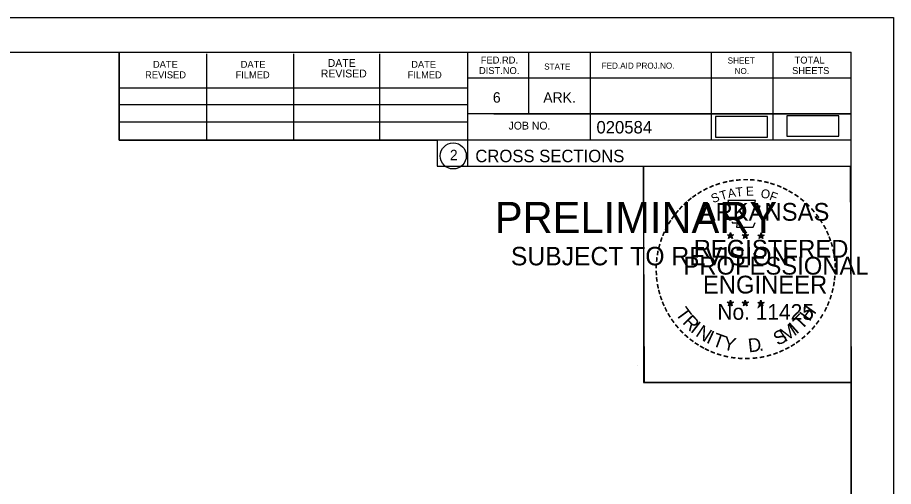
# Model space of a CAD drawing. Extents: x 1312042 to 1371461, y 379929 to 1834241.
# Drawn here: x 1371362.8 to 1371461.2, y 380302.9 to 380355.6 of the extents above; entities that cross this region are included whole.
import ezdxf

# ---------------------------------------------------------------- set-up
doc = ezdxf.new("R2010")
doc.units = 0
for name, color, linetype in [('Default', 7, 'Continuous'), ('R_Border', 7, 'Continuous'), ('R_Border PE', 7, 'Continuous'), ('R_Border Prem', 7, 'Continuous'), ('R_No Plot', 7, 'Continuous')]:
    doc.layers.add(name, color=color, linetype=linetype)

msp = doc.modelspace()

# ---------------------------------------------------------------- linework, layer by layer
at = {"layer": 'Default'}
for points in [[(1371441.216, 380342.147), (1371447.049, 380342.147), (1371447.049, 380344.458), (1371441.216, 380344.458)], [(1371449.239, 380342.253), (1371455.073, 380342.253), (1371455.073, 380344.564), (1371449.239, 380344.564)]]:
    msp.add_lwpolyline(points, close=True, dxfattribs=at)
at = {"layer": 'R_Border'}
for p, q in [((1371140.277, 380351.707), (1371456.457, 380351.707)), ((1371374.197, 380341.827), (1371374.197, 380351.707)), ((1371384.057, 380341.827), (1371384.057, 380351.507)), ((1371393.817, 380341.827), (1371393.817, 380351.507)), ((1371403.497, 380341.827), (1371403.497, 380351.507)), ((1371413.357, 380351.707), (1371413.357, 380338.907)), ((1371420.197, 380351.707), (1371420.197, 380344.767)), ((1371427.137, 380351.707), (1371427.137, 380341.827)), ((1371440.717, 380351.707), (1371440.717, 380341.827)), ((1371447.657, 380351.707), (1371447.657, 380341.827)), ((1371456.457, 380146.247), (1371456.457, 380351.707)), ((1371456.457, 380348.767), (1371413.357, 380348.767)), ((1371456.457, 380348.787), (1371456.457, 380348.787)), ((1371374.197, 380347.687), (1371413.357, 380347.687)), ((1371374.197, 380345.827), (1371413.357, 380345.827)), ((1371456.457, 380344.767), (1371413.357, 380344.767)), ((1371416.317, 380344.767), (1371456.457, 380344.767)), ((1371374.197, 380341.827), (1371374.197, 380343.887)), ((1371374.197, 380343.887), (1371413.357, 380343.887)), ((1371456.457, 380341.827), (1371374.197, 380341.827)), ((1371413.357, 380338.907), (1371456.457, 380338.907))]:
    msp.add_line(p, q, dxfattribs=at)
msp.add_circle((1371411.743, 380340.043), 1.467, dxfattribs=at)
at = {"layer": 'R_Border PE'}
for p, q in [((1371442.541, 380331.162), (1371442.89, 380331.051)), ((1371442.541, 380331.162), (1371442.794, 380331.117)), ((1371442.541, 380331.162), (1371442.778, 380331.04)), ((1371442.674, 380330.754), (1371442.89, 380331.051)), ((1371442.674, 380330.754), (1371442.8, 380330.998)), ((1371442.674, 380330.754), (1371442.888, 380330.971)), ((1371442.89, 380331.416), (1371442.849, 380331.164)), ((1371443.103, 380330.754), (1371442.888, 380330.968)), ((1371442.89, 380331.051), (1371442.89, 380331.416)), ((1371442.89, 380331.416), (1371442.939, 380331.166)), ((1371443.237, 380331.162), (1371442.89, 380331.051)), ((1371443.103, 380330.754), (1371442.89, 380331.051)), ((1371443.237, 380331.162), (1371442.951, 380331.113)), ((1371443.103, 380330.754), (1371442.966, 380331.045)), ((1371443.237, 380331.162), (1371443.033, 380331.06)), ((1371444.211, 380331.162), (1371444.56, 380331.051)), ((1371444.211, 380331.162), (1371444.464, 380331.117)), ((1371444.211, 380331.162), (1371444.448, 380331.04)), ((1371444.344, 380330.754), (1371444.56, 380331.051)), ((1371444.344, 380330.754), (1371444.47, 380330.998)), ((1371444.344, 380330.754), (1371444.558, 380330.971)), ((1371444.56, 380331.416), (1371444.519, 380331.164)), ((1371444.773, 380330.754), (1371444.558, 380330.968)), ((1371444.56, 380331.051), (1371444.56, 380331.416)), ((1371444.56, 380331.416), (1371444.609, 380331.166)), ((1371444.907, 380331.162), (1371444.56, 380331.051)), ((1371444.773, 380330.754), (1371444.56, 380331.051)), ((1371444.907, 380331.162), (1371444.621, 380331.113)), ((1371444.773, 380330.754), (1371444.636, 380331.045)), ((1371444.907, 380331.162), (1371444.703, 380331.06)), ((1371445.975, 380331.15), (1371446.324, 380331.039)), ((1371445.975, 380331.15), (1371446.228, 380331.105)), ((1371445.975, 380331.15), (1371446.212, 380331.028)), ((1371446.108, 380330.742), (1371446.324, 380331.039)), ((1371446.108, 380330.742), (1371446.234, 380330.986)), ((1371446.108, 380330.742), (1371446.322, 380330.959)), ((1371446.324, 380331.404), (1371446.283, 380331.152)), ((1371446.537, 380330.742), (1371446.322, 380330.956)), ((1371446.324, 380331.039), (1371446.324, 380331.404)), ((1371446.324, 380331.404), (1371446.373, 380331.154)), ((1371446.671, 380331.15), (1371446.324, 380331.039)), ((1371446.537, 380330.742), (1371446.324, 380331.039)), ((1371446.671, 380331.15), (1371446.385, 380331.101)), ((1371446.537, 380330.742), (1371446.4, 380331.033)), ((1371446.671, 380331.15), (1371446.467, 380331.048)), ((1371442.537, 380323.589), (1371442.886, 380323.478)), ((1371442.537, 380323.589), (1371442.79, 380323.544)), ((1371442.537, 380323.589), (1371442.774, 380323.467)), ((1371442.886, 380323.843), (1371442.845, 380323.591)), ((1371442.886, 380323.478), (1371442.886, 380323.843)), ((1371442.886, 380323.843), (1371442.935, 380323.593)), ((1371443.233, 380323.589), (1371442.886, 380323.478)), ((1371443.233, 380323.589), (1371442.947, 380323.54)), ((1371443.233, 380323.589), (1371443.029, 380323.487)), ((1371444.206, 380323.589), (1371444.555, 380323.478)), ((1371444.206, 380323.589), (1371444.459, 380323.544)), ((1371444.206, 380323.589), (1371444.443, 380323.467)), ((1371444.555, 380323.843), (1371444.514, 380323.591)), ((1371444.555, 380323.478), (1371444.555, 380323.843)), ((1371444.555, 380323.843), (1371444.604, 380323.593)), ((1371444.902, 380323.589), (1371444.555, 380323.478)), ((1371444.902, 380323.589), (1371444.616, 380323.54)), ((1371444.902, 380323.589), (1371444.698, 380323.487)), ((1371445.973, 380323.579), (1371446.322, 380323.468)), ((1371445.973, 380323.579), (1371446.226, 380323.534)), ((1371445.973, 380323.579), (1371446.21, 380323.457)), ((1371446.322, 380323.833), (1371446.281, 380323.581)), ((1371446.322, 380323.468), (1371446.322, 380323.833)), ((1371446.322, 380323.833), (1371446.371, 380323.583)), ((1371446.669, 380323.579), (1371446.322, 380323.468)), ((1371446.669, 380323.579), (1371446.383, 380323.53)), ((1371446.669, 380323.579), (1371446.465, 380323.477)), ((1371442.67, 380323.181), (1371442.886, 380323.478)), ((1371442.67, 380323.181), (1371442.796, 380323.425)), ((1371442.67, 380323.181), (1371442.884, 380323.398)), ((1371443.099, 380323.181), (1371442.884, 380323.395)), ((1371443.099, 380323.181), (1371442.886, 380323.478)), ((1371443.099, 380323.181), (1371442.962, 380323.472)), ((1371444.339, 380323.181), (1371444.555, 380323.478)), ((1371444.339, 380323.181), (1371444.465, 380323.425)), ((1371444.339, 380323.181), (1371444.553, 380323.398)), ((1371444.768, 380323.181), (1371444.553, 380323.395)), ((1371444.768, 380323.181), (1371444.555, 380323.478)), ((1371444.768, 380323.181), (1371444.631, 380323.472)), ((1371446.106, 380323.171), (1371446.322, 380323.468)), ((1371446.106, 380323.171), (1371446.232, 380323.415)), ((1371446.106, 380323.171), (1371446.32, 380323.388)), ((1371446.535, 380323.171), (1371446.32, 380323.385)), ((1371446.535, 380323.171), (1371446.322, 380323.468)), ((1371446.535, 380323.171), (1371446.398, 380323.462))]:
    msp.add_line(p, q, dxfattribs=at)
for points in [[(1371442.582, 380335.04), (1371442.851, 380334.213)], [(1371446.093, 380334.118), (1371446.235, 380334.402), (1371445.55, 380334.378), (1371445.698, 380335.04), (1371442.582, 380335.04)], [(1371443.074, 380332.617), (1371443.074, 380332.53), (1371443.637, 380332.511), (1371443.583, 380332.038), (1371445.453, 380332.038), (1371445.654, 380332.574)], [(1371442.89, 380331.416), (1371443.103, 380330.754), (1371442.541, 380331.162), (1371443.237, 380331.162), (1371442.674, 380330.754), (1371442.89, 380331.416)], [(1371444.56, 380331.416), (1371444.773, 380330.754), (1371444.211, 380331.162), (1371444.907, 380331.162), (1371444.344, 380330.754), (1371444.56, 380331.416)], [(1371446.324, 380331.404), (1371446.537, 380330.742), (1371445.975, 380331.15), (1371446.671, 380331.15), (1371446.108, 380330.742), (1371446.324, 380331.404)], [(1371442.886, 380323.843), (1371443.099, 380323.181), (1371442.537, 380323.589), (1371443.233, 380323.589), (1371442.67, 380323.181), (1371442.886, 380323.843)], [(1371444.555, 380323.843), (1371444.768, 380323.181), (1371444.206, 380323.589), (1371444.902, 380323.589), (1371444.339, 380323.181), (1371444.555, 380323.843)], [(1371446.322, 380323.833), (1371446.535, 380323.171), (1371445.973, 380323.579), (1371446.669, 380323.579), (1371446.106, 380323.171), (1371446.322, 380323.833)]]:
    msp.add_lwpolyline(points, dxfattribs=at)
for centre, radius in [((1371442.889, 380331.05), 0.172), ((1371442.889, 380331.05), 0.145), ((1371442.889, 380331.05), 0.116), ((1371442.889, 380331.05), 0.0991), ((1371442.889, 380331.05), 0.0747), ((1371442.889, 380331.05), 0.0495), ((1371442.889, 380331.05), 0.0296), ((1371444.559, 380331.05), 0.172), ((1371444.559, 380331.05), 0.145), ((1371444.559, 380331.05), 0.116), ((1371444.559, 380331.05), 0.0991), ((1371444.559, 380331.05), 0.0747), ((1371444.559, 380331.05), 0.0495), ((1371444.559, 380331.05), 0.0296), ((1371446.323, 380331.038), 0.172), ((1371446.323, 380331.038), 0.145), ((1371446.323, 380331.038), 0.116), ((1371446.323, 380331.038), 0.0991), ((1371446.323, 380331.038), 0.0747), ((1371446.323, 380331.038), 0.0495), ((1371446.323, 380331.038), 0.0296), ((1371442.885, 380323.477), 0.172), ((1371442.885, 380323.477), 0.145), ((1371442.885, 380323.477), 0.116), ((1371442.885, 380323.477), 0.0991), ((1371442.885, 380323.477), 0.0747), ((1371444.554, 380323.477), 0.172), ((1371444.554, 380323.477), 0.145), ((1371444.554, 380323.477), 0.116), ((1371444.554, 380323.477), 0.0991), ((1371444.554, 380323.477), 0.0747), ((1371446.321, 380323.467), 0.172), ((1371446.321, 380323.467), 0.145), ((1371446.321, 380323.467), 0.116), ((1371446.321, 380323.467), 0.0991), ((1371442.885, 380323.477), 0.0495), ((1371442.885, 380323.477), 0.0296), ((1371444.554, 380323.477), 0.0495), ((1371444.554, 380323.477), 0.0296), ((1371446.321, 380323.467), 0.0747), ((1371446.321, 380323.467), 0.0495), ((1371446.321, 380323.467), 0.0296)]:
    msp.add_circle(centre, radius, dxfattribs=at)
at = {"layer": 'R_No Plot'}
for p, q in [((1371127.876, 380355.601), (1371461.209, 380355.601)), ((1371432.491, 380316.451), (1371432.491, 380316.451))]:
    msp.add_line(p, q, dxfattribs=at)
for points in [[(1371127.869, 380355.601), (1371461.209, 380355.601), (1371461.209, 380142.264), (1371127.869, 380142.264)], [(1371374.197, 380351.707), (1371374.197, 380341.827), (1371409.929, 380341.827), (1371409.929, 380338.907), (1371433.128, 380338.907), (1371433.128, 380314.574), (1371456.457, 380314.574), (1371456.457, 380146.247), (1371140.277, 380146.247), (1371140.277, 380351.707)], [(1371433.128, 380338.907), (1371456.336, 380338.907), (1371456.457, 380314.574), (1371433.249, 380314.574)]]:
    msp.add_lwpolyline(points, close=True, dxfattribs=at)

# ---------------------------------------------------------------- texts
at = {"layer": 'R_Border'}
for s, height, p in [('FED.RD.', 0.7819, (1371414.837, 380350.427)), ('SHEET', 0.684, (1371442.577, 380350.427)), ('TOTAL', 0.7819, (1371450.097, 380350.427)), ('DATE', 0.7819, (1371377.997, 380349.947)), ('DATE', 0.7819, (1371387.857, 380349.947)), ('DATE', 0.8792, (1371397.637, 380350.047)), ('DATE', 0.7819, (1371407.017, 380349.947)), ('STATE', 0.684, (1371421.957, 380349.747)), ('FED.AID PROJ.NO.', 0.684, (1371428.417, 380349.847)), ('REVISED', 0.7819, (1371377.117, 380348.767)), ('FILMED', 0.7819, (1371387.277, 380348.767)), ('REVISED', 0.8792, (1371396.857, 380348.867)), ('FILMED', 0.7819, (1371406.617, 380348.767)), ('DIST.NO.', 0.7819, (1371414.637, 380349.247)), ('NO.', 0.684, (1371443.357, 380349.247)), ('SHEETS', 0.7819, (1371449.817, 380349.247)), ('6', 1.172, (1371416.197, 380346.027)), ('ARK.', 1.1723, (1371421.857, 380346.027)), ('JOB NO.', 0.8792, (1371417.957, 380343.007)), ('020584', 1.4, (1371427.833, 380342.566)), ('2', 1.172, (1371411.361, 380339.556)), ('CROSS SECTIONS', 1.4, (1371414.22, 380339.337))]:
    msp.add_text(s, height=height, rotation=360, dxfattribs=at).set_placement(p)
at = {"layer": 'R_Border PE'}
for s, height, rotation, p in [('-', 1.6, 10.21935, (1371442.758, 380336.57)), ('-', 1.6, 5.89682, (1371443.487, 380336.68)), ('-', 1.6, 0.18623, (1371444.259, 380336.752)), ('-', 1.6, 357.74304, (1371444.982, 380336.739)), ('-', 1.6, 352.16172, (1371445.726, 380336.683)), ('-', 1.6, 28.79182, (1371440.063, 380335.581)), ('-', 1.6, 24.30721, (1371440.696, 380335.898)), ('-', 1.6, 19.17608, (1371441.33, 380336.167)), ('-', 1.6, 13.63015, (1371442.08, 380336.408)), ('A', 1, 11.21318, (1371442.677, 380335.3)), ('T', 1, 6.02276, (1371443.526, 380335.466)), ('E', 1, 0.83234, (1371444.631, 380335.576)), ('-', 1.6, 347.20489, (1371446.445, 380336.569)), ('-', 1.6, 342.3362, (1371447.08, 380336.414)), ('-', 1.6, 337.85509, (1371447.815, 380336.191)), ('-', 1.6, 334.12109, (1371448.446, 380335.92)), ('-', 1.6, 38.95066, (1371438.412, 380334.438)), ('-', 1.6, 36.23174, (1371438.888, 380334.816)), ('-', 1.6, 34.06357, (1371439.466, 380335.211)), ('S', 1, 21.59401, (1371440.937, 380334.718)), ('T', 1, 16.4036, (1371441.851, 380335.049)), ('O', 1, 350.4515, (1371446.235, 380335.366)), ('F', 1, 340.07066, (1371447.189, 380335.138)), ('-', 1.6, 329.64089, (1371449.025, 380335.637)), ('-', 1.6, 325.86266, (1371449.668, 380335.276)), ('-', 1.6, 48.42305, (1371437.531, 380333.543)), ('-', 1.6, 42.96224, (1371437.979, 380334.021)), ('ARKANSAS', 2, 360, (1371439.435, 380332.752)), ('-', 1.6, 320.52971, (1371450.278, 380334.85)), ('-', 1.6, 315.57859, (1371450.877, 380334.362)), ('-', 1.6, 54.23247, (1371436.715, 380332.49)), ('-', 1.6, 50.61417, (1371437.128, 380333.057)), ('-', 1.6, 309.87973, (1371451.446, 380333.812)), ('-', 1.6, 306.65218, (1371451.971, 380333.21)), ('-', 1.6, 58.07063, (1371436.39, 380331.963)), ('-', 1.4, 303.67529, (1371452.457, 380332.642)), ('-', 1.6, 67.77427, (1371435.818, 380330.738)), ('-', 1.6, 62.87135, (1371436.077, 380331.349)), ('-', 1.6, 299.66835, (1371452.776, 380332.035)), ('-', 1.6, 294.66279, (1371453.1, 380331.423)), ('-', 1.6, 72.39447, (1371435.599, 380330.108)), ('REGISTERED', 2, 360, (1371438.757, 380328.603)), ('DWB', 0.01, 360, (1371442.878, 380331.046)), ('DWB', 0.01, 360, (1371444.547, 380331.046)), ('DWB', 0.01, 360, (1371446.312, 380331.035)), ('-', 1.6, 290.57283, (1371453.357, 380330.846)), ('-', 1.6, 75.46096, (1371435.402, 380329.394)), ('-', 1.6, 285.12326, (1371453.591, 380330.266)), ('-', 1.6, 280.54934, (1371453.791, 380329.524)), ('-', 1.6, 85.18634, (1371435.194, 380327.99)), ('-', 1.6, 81.20126, (1371435.27, 380328.681)), ('PROFESSIONAL', 2, 360, (1371437.609, 380326.699)), ('-', 1.6, 276.59616, (1371453.953, 380328.756)), ('-', 1.6, 89.06224, (1371435.169, 380327.289)), ('-', 1.6, 274.33011, (1371454.013, 380328.034)), ('-', 1.6, 94.19588, (1371435.204, 380326.564)), ('ENGINEER', 2, 360, (1371439.796, 380324.574)), ('-', 1.6, 263.5172, (1371454.028, 380326.736)), ('-', 1.6, 269.94067, (1371454.047, 380327.402)), ('-', 1.6, 98.94793, (1371435.276, 380325.897)), ('-', 1.6, 101.71495, (1371435.411, 380325.164)), ('-', 1.6, 260.99529, (1371453.957, 380326.082)), ('-', 1.6, 105.45785, (1371435.573, 380324.569)), ('-', 1.6, 255.7626, (1371453.847, 380325.404)), ('-', 1.6, 109.08742, (1371435.788, 380323.938)), ('-', 1.6, 114.06432, (1371436.042, 380323.342)), ('-', 1.6, 247.88866, (1371453.443, 380324.011)), ('-', 1.6, 252.86809, (1371453.666, 380324.684)), ('-', 1.6, 115.72885, (1371436.347, 380322.724)), ('T', 1.54, 306.04056, (1371436.646, 380322.316)), ('No. 11425', 1.757, 360, (1371441.424, 380321.623)), ('DWB', 0.01, 360, (1371442.874, 380323.473)), ('DWB', 0.01, 360, (1371444.543, 380323.473)), ('DWB', 0.01, 360, (1371446.31, 380323.463)), ('H', 1.54, 54.60883, (1371451.766, 380321.351)), ('-', 1.6, 244.61971, (1371453.181, 380323.382)), ('-', 1.6, 120.44712, (1371436.704, 380322.138)), ('-', 1.6, 125.89344, (1371437.107, 380321.577)), ('R', 1.54, 314.00497, (1371437.409, 380321.268)), ('T', 1.54, 46.64442, (1371450.877, 380320.409)), ('-', 1.6, 233.84524, (1371452.385, 380321.977)), ('-', 1.6, 239.07125, (1371452.787, 380322.63)), ('-', 1.6, 130.71812, (1371437.569, 380321.025)), ('I', 1.54, 321.96938, (1371438.309, 380320.336)), ('N', 1.54, 326.50021, (1371438.876, 380319.865)), ('M', 1.54, 32.65632, (1371449.031, 380319.084)), ('I', 1.54, 42.11359, (1371450.315, 380319.931)), ('-', 1.6, 231.25377, (1371451.955, 380321.411)), ('-', 1.6, 134.22381, (1371438.086, 380320.48)), ('-', 1.6, 138.93382, (1371438.611, 380320.016)), ('I', 1.54, 335.36034, (1371440.084, 380319.079)), ('T', 1.54, 339.89117, (1371440.745, 380318.751)), ('Y', 1.54, 347.85558, (1371441.962, 380318.306)), ('S', 1.54, 26.9312, (1371448.192, 380318.678)), ('-', 1.6, 221.08509, (1371450.954, 380320.338)), ('-', 1.6, 225.76533, (1371451.476, 380320.847)), ('-', 1.6, 144.64634, (1371439.167, 380319.61)), ('-', 1.6, 148.08978, (1371439.728, 380319.239)), ('-', 1.6, 151.57039, (1371440.307, 380318.914)), ('D', 1.54, 6.39691, (1371444.947, 380317.947)), ('-', 1.6, 212.24909, (1371449.871, 380319.479)), ('-', 1.6, 215.73633, (1371450.405, 380319.866)), ('-', 1.6, 154.60019, (1371440.829, 380318.667)), ('-', 1.6, 158.56121, (1371441.453, 380318.413)), ('-', 1.6, 162.79826, (1371442.14, 380318.2)), ('-', 1.6, 167.55551, (1371442.855, 380318.036)), ('.', 1.54, 13.76417, (1371446.139, 380318.075)), ('-', 1.6, 195.47429, (1371447.393, 380318.299)), ('-', 1.6, 200.71842, (1371448.07, 380318.541)), ('-', 1.6, 204.25161, (1371448.689, 380318.814)), ('-', 1.6, 207.35684, (1371449.313, 380319.133)), ('-', 1.6, 173.11546, (1371443.627, 380317.926)), ('-', 1.6, 176.51827, (1371444.375, 380317.873)), ('-', 1.6, 181.59176, (1371445.119, 380317.892)), ('-', 1.6, 185.81666, (1371445.928, 380317.968)), ('-', 1.6, 191.28576, (1371446.664, 380318.1))]:
    msp.add_text(s, height=height, rotation=rotation, dxfattribs=at).set_placement(p)
at = {"layer": 'R_Border Prem'}
for s, height, p in [('PRELIMINARY', 3.5, (1371416.408, 380331.37)), ('DWB', 0.01, (1371417.154, 380333.219)), ('SUBJECT TO REVISION', 2.07511, (1371418.217, 380327.741))]:
    msp.add_text(s, height=height, rotation=360, dxfattribs=at).set_placement(p)

doc.saveas('drawing.dxf')
